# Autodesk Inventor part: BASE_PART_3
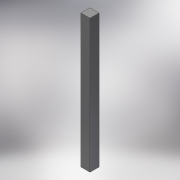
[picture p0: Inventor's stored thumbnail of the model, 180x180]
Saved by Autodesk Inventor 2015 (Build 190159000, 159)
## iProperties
Created: 2014-08
Part Number: BASE_PART_3
Material: Steel, Mild
Document SubType Name: Modeling
Designer: lakshayg
Density: 7.85 g/cm^3
Appearance: Semi-Polished
Mass: 200.985 g
Surface Area: 88.224 cm^2
Volume: 25.6032 cm^3
Author: lakshayg
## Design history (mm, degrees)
sketch "Sketch1"
  geometry: L1 (0, 0)-(-12, 0); L2 (-12, 0)-(-12, -177.8); L3 (-12, -177.8)-(0, -177.8); L4 (0, -177.8)-(0, 0)
  constraints: 8 end point, 2 parallel, 1 horizontal, 1 perpendicular
  dimensions: "d0" = 177.8 distance of L3.end L1.start; "d1" = 12 distance of L1.start L1.end
extrude "Extrusion1" new body sketch "Sketch1" distance "d2" = 12; taper "d3" = 0 deg
body "Solid1"
